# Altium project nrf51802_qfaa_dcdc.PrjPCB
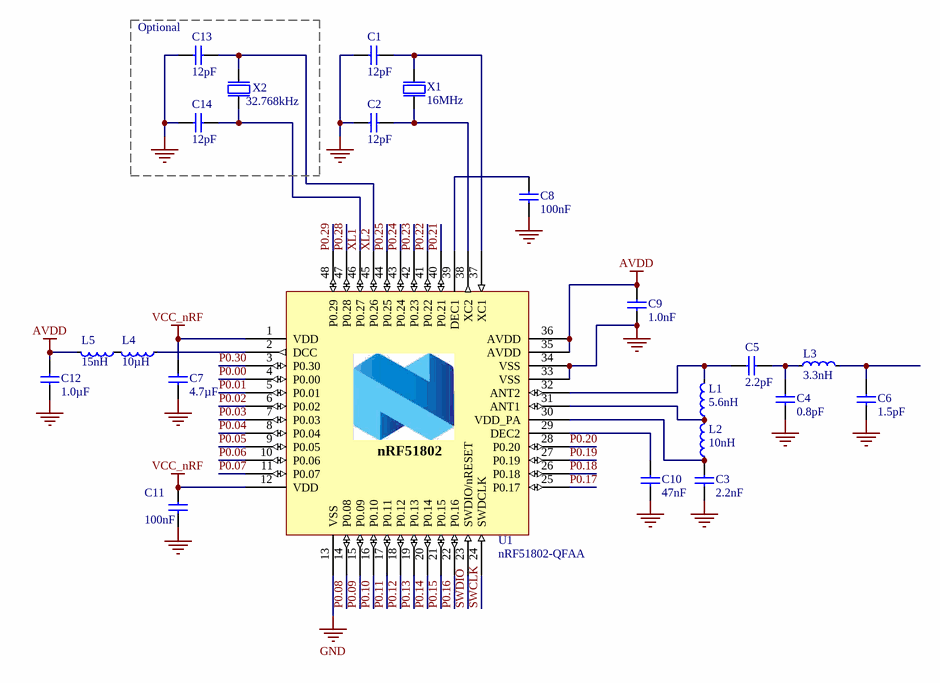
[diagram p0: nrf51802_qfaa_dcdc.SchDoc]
1 sheet, 22 parts. Net scope: global (net labels, ports and power ports of the same name join across sheets).
Board file: nrf51802_qfaa_dcdc.PcbDoc

## Sheet nrf51802_qfaa_dcdc.SchDoc: nRF51802-QFAA Reference Layout (DCDC)
size A4; Revision: 1.0; SheetNumber: 1; SheetTotal: 1; DrawnBy: RUBR; DocumentSize: A4; PCAName: nRF51802-QFAA Reference Layout (DCDC)

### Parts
C1  12pF  [CAPC1005X04L]
C2  12pF  [CAPC1005X04L]
C3  2.2nF  [CAPC1005X04L]
C4  0.8pF  [CAPC1005X04L]
C5  2.2pF  [CAPC1005X04L]
C6  1.5pF  [CAPC1005X04L]
C7  4.7µF  [CAPC1608X06L]
C8  100nF  [CAPC1005X04L]
C9  1.0nF  [CAPC1005X04L]
C10  47nF  [CAPC1005X04L]
C11  100nF  [CAPC1005X04L]
C12  1.0µF  [CAPC1608X06L]
C13  12pF  [CAPC1005X04L]
C14  12pF  [CAPC1005X04L]
L1  5.6nH  [INDC1005X04L]
L2  10nH  [INDC1005X04L]
L3  3.3nH  [INDC1005X04L]
L4  10µH  [INDC1608X06L]
L5  15nH  [INDC1005X04L]
U1  nRF51802-QFAA  [QFN40P600X600X90-48N]
X1  16MHz  [BT-XTAL_2520]
X2  32.768kHz  [XTAL_3215]

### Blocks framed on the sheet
Optional: C13 C14 X2

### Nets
AVDD: C9.1 C12.2 L5.2 U1.35(AVDD) U1.36(AVDD)
GND: C1.2 C2.2 C3.2 C4.2 C6.2 C7.2 C8.2 C9.2 C10.2 C11.2 C12.1 C13.1 C14.1 U1.13(VSS) U1.33(VSS) U1.34(VSS) U1.49 X1.2(GND) X1.4(GND)
VCC_nRF: C7.1 C11.1 U1.1(VDD) U1.12(VDD)
P0.00: U1.4(P0.00)
P0.01: U1.5(P0.01)
P0.02: U1.6(P0.02)
P0.03: U1.7(P0.03)
P0.04: U1.8(P0.04)
P0.05: U1.9(P0.05)
P0.06: U1.10(P0.06)
P0.07: U1.11(P0.07)
P0.08: U1.14(P0.08)
P0.09: U1.15(P0.09)
P0.10: U1.16(P0.10)
P0.11: U1.17(P0.11)
P0.12: U1.18(P0.12)
P0.13: U1.19(P0.13)
P0.14: U1.20(P0.14)
P0.15: U1.21(P0.15)
P0.16: U1.22(P0.16)
P0.17: U1.25(P0.17)
P0.18: U1.26(P0.18)
P0.19: U1.27(P0.19)
P0.20: U1.28(P0.20)
P0.21: U1.40(P0.21)
P0.22: U1.41(P0.22)
P0.23: U1.42(P0.23)
P0.24: U1.43(P0.24)
P0.25: U1.44(P0.25)
P0.28: U1.47(P0.28)
P0.29: U1.48(P0.29)
P0.30: U1.3(P0.30)
SWCLK: U1.24(SWDCLK)
SWDIO: U1.23(SWDIO/nRESET)
XL1: C14.2 U1.46(P0.27) X2.2(out)
XL2: C13.2 U1.45(P0.26) X2.1(inp)
NetC1_1: C1.1 U1.37(XC1) X1.1(inp)
NetC2_1: C2.1 U1.38(XC2) X1.3(out)
NetC3_1: C3.1 L2.1 U1.30(VDD_PA)
NetC4_1: C4.1 C5.2 L3.1
NetC5_1: C5.1 L1.2 U1.32(ANT2)
NetC6_1: C6.1 L3.2
NetC8_1: C8.1 U1.39(DEC1)
NetC10_1: C10.1 U1.29(DEC2)
NetL1_1: L1.1 L2.2 U1.31(ANT1)
NetL4_1: L4.1 U1.2(DCC)
NetL4_2: L4.2 L5.1

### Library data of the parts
C1 C2 C13 C14 = C0402-12p: Capacitor, NP0, ±2%; Note: 50V; Artikkelnr Noca: 20029159; Artikkelnr Simpro: N.A.
C3 = C0402-2n2: Capacitor, X7R, ±10%; Note: 50V; Artikkelnr Noca: 20039221; Artikkelnr Simpro: N.A.
C4 = C0402-0.8p: Capacitor, NP0, ±5%; Note: 50V; Artikkelnr Noca: 20029147; Artikkelnr Simpro: N.A.
C5 = C0402-2.2p: Capacitor, NP0, ±0.1pF; Note: 50V; Artikkelnr Noca: 20029145; Artikkelnr Simpro: N.A.
C6 = C0402-1.5p: Capacitor, NP0, ±0.1pF; Note: 50V; Artikkelnr Noca: 20029139; Artikkelnr Simpro: N.A.
C7 = C0603-4µ7: Capacitor, X5R, ±10%; Note: 6.3V; Artikkelnr Noca: 20069060; Artikkelnr Simpro: N.A.
C8 C11 = C0402-100n: Capacitor, X7R, ±10%; Note: 16V; Artikkelnr Noca: 20039200; Artikkelnr Simpro: N.A.
C9 = C0402-1n0: Capacitor, X7R, ±10%; Note: 50V; Artikkelnr Noca: 20039223; Artikkelnr Simpro: N.A.
C10 = C0402-47n: Capacitor, X7R, ±10%; Note: Chip Cap 10%; Artikkelnr Noca: 20039389; Artikkelnr Simpro: N.A.
C12 = C0603-1µ0: Capacitor, X7R, ±10%; Note: 16V; Artikkelnr Noca: 20039335; Artikkelnr Simpro: N.A.
L1 = L0402-5n6: High frequency chip inductor ±5%; Manufacturer: Murata; Manufacturer Part Number: LQP15MN5N6B02D; Artikkelnr Noca: 33029161; Artikkelnr Simpro: N.A.
L2 = L0402-10n: High frequency chip inductor ±5%; Manufacturer: Murata; Manufacturer Part Number: LQP15MN10NG02D; Artikkelnr Noca: 33029425; Artikkelnr Simpro: N.A.
L3 = L0402-3n3: High frequency chip inductor ±5%; Manufacturer: Murata; Manufacturer Part Number: LQP15MN3N3B02D; Artikkelnr Noca: 33029369; Artikkelnr Simpro: N.A.
L4 = L0603-10µ: Chip inductor, IDC,min = 50 mA, ±20%; Manufacturer: Taiyo Yuden; Manufacturer Part Number: LBMF1608T100K; 2nd source part number: 178-6105; Note: LBMF1608T100K 10µH 80mA 0603; Artikkelnr Noca: 33029314; Artikkelnr Simpro: N.A.
L5 = L0402-15n: High frequency chip inductor ±10%; Manufacturer: Taiyo Yuden; Manufacturer Part Number: HK100515NJ-T; 2nd source part number: 658-1328; Artikkelnr Noca: 33029323; Artikkelnr Simpro: N.A.
U1 = nRF51802-QFAA: Multi-protocol Bluetooth Low Energy and 2.4GHz proprietary system-on-chip; Manufacturer: Nordic Semiconductor; Note: nRF51802 - QFN48 6x6 0.4mm pitch; Artikkelnr Noca: N.A.
X1 = XTAL_SMD2520_16MHz_8pF_NDK: XTAL SMD 2520, 16MHz, 8pF, ±40ppm; Manufacturer: NDK; Manufacturer Part Number: NX2520SA/16MHz/EXS00A-CS06713; Note: XTAL SMD 16.000MHz; Artikkelnr Noca: 22019192; Artikkelnr Simpro: N.A.
X2 = XTAL_FC-135 32.768k: XTAL SMD 3215, 32.768kHz, 9pF, ±20ppm; Manufacturer: Epson Toyocom; Manufacturer Part Number: FC-135 32.768KHZ ±20PPM,9.0PF; 2nd source part number: 127-8037; Note: XTAL SMD 32.768kHz, 3215; Artikkelnr Noca: 22019091; Artikkelnr Simpro: N.A.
